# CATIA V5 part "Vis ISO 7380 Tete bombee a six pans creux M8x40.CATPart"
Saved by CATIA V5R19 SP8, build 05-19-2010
Part number: Vis ISO 7380 Tete bombee a six pans creux M8x40
Nomenclature: 10
Source: Unknown
Description: PART-pn48560052-DESC
Material "Acier": density 7860 kg/m3, Young's modulus 2e+11 Pa, Poisson ratio 0.266, thermal expansion 1.17e-05 1/K
Material "Acier": density 7860 kg/m3, Young's modulus 2e+11 Pa, Poisson ratio 0.266, thermal expansion 1.17e-05 1/K
Bounding box of the stored display mesh (mm): x -4.4 to 40, y -7 to 7, z -7 to 7
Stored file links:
  C:\Users\rphgr\Desktop\0_Tapis_TC520B_vitesse\Vis ISO 7380 Tete bombee a six pans creux M8x40.CATPart
  C:\Program Files\Dassault Systemes\B19\win_b64\reffiles\standard\MetricThickPitch.txt
  D:\Programmes\DassaultSysteme\win_b64\startup\materials\French\Catalog.CATMaterial
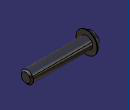
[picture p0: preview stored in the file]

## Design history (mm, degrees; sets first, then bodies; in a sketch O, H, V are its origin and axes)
AxisSystem1: origin (0, 0, 0), X (1, 0, 0), Y (0, 1, 0), Z (0, 0, 1)
Body1 "Tête" (main body), material "Acier"
  Solid1 "pn48560052": solid without history
  Split1: SplitPlane face of Solid1
Body2, material "Acier"
  Sketch1 on XY plane of AxisSystem1, origin (0, 0, 0), H (1, 0, 0), V (0, 1, 0)
    line L1 (40, 0) -> (40, 4)
    line L2 (40, 4) -> (0, 4)
    line L3 (0, 4) -> (0, 0)
    axis line L4 (0, 0) -> (56.1618, 0)
    reference intersected line E1 (0, 7) -> (0, -7) from face of Split1
    distance L1 E1 = 40
    "Radius" L2 L4 = 4
    horizontal: L2 H, L4 H
    vertical: L1 V, L3 V
  Shaft1: profile Sketch1, axis Sketch1.L4, angle 360
  Thread1: "M8", diameter 8, depth 12, pitch 1.25, on face of Shaft1 from Sketch1.L2, from face of Shaft1 from Sketch1.L1
  Chamfer1: length 1, angle 45, on edge [face of Shaft1 from Sketch1.L2 | face of Shaft1 from Sketch1.L1]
